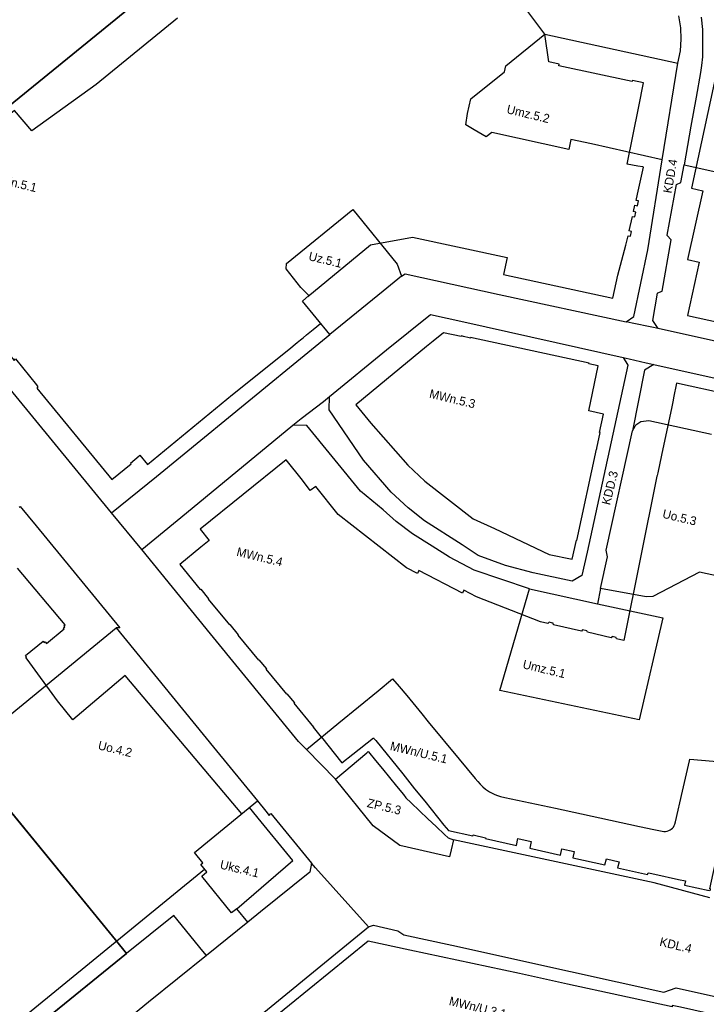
# Model space of a CAD drawing. Extents: x 7429686 to 7432896, y 5547954 to 5550600.
# Drawn here: x 7430853.5 to 7431167.9, y 5549633.8 to 5550085.1 of the extents above; entities that cross this region are included whole.
import ezdxf

# ---------------------------------------------------------------- set-up
doc = ezdxf.new("R2010")
doc.units = 0
for name, color, linetype in [('granica planu', 7, 'Continuous'), ('linie rozgraniczające', 7, 'Continuous'), ('obowiązująca linia zabudowy', 7, 'Continuous'), ('oznaczenia przeznaczeń', 7, 'Continuous')]:
    doc.layers.add(name, color=color, linetype=linetype)

msp = doc.modelspace()

# ---------------------------------------------------------------- linework, layer by layer
at = {"layer": 'granica planu'}
msp.add_lwpolyline([(7430718.8, 5549938.87), (7430746.03, 5549960.72), (7430798.13, 5550004.59), (7430923.69, 5550106.91), (7431051.87, 5550217.85), (7431132.58, 5550281.48)], dxfattribs=at)
at = {"layer": 'linie rozgraniczające'}
for p, q in [((7430897.36, 5549663.3), (7430837.38, 5549736.73)), ((7430902.46, 5549657.05), (7430897.36, 5549663.3)), ((7430805.78, 5549578.76), (7430902.46, 5549657.05))]:
    msp.add_line(p, q, dxfattribs=at)
for points in [[(7430973.53, 5550150.05), (7430923.69, 5550106.91), (7430798.13, 5550004.59), (7430788.04, 5549996.1)], [(7431156.31, 5550081.44), (7431155.42, 5550086.86)], [(7431165.53, 5550086.29), (7431166.21, 5550080.63)], [(7431156.47, 5550076.26), (7431156.31, 5550081.44)], [(7431076.18, 5550063.91), (7431093.98, 5550078.43)], [(7431093.98, 5550078.43), (7431154.96, 5550065.25)], [(7431166.21, 5550080.63), (7431166.23, 5550068.12)], [(7431156.14, 5550070.9), (7431156.47, 5550076.26)], [(7431154.96, 5550065.25), (7431156.14, 5550070.9)], [(7431166.23, 5550068.12), (7431165.7, 5550064.07)], [(7431075.58, 5550061.25), (7431076.18, 5550063.91)], [(7431147.66, 5550020.92), (7431154.96, 5550065.25)], [(7431165.7, 5550064.07), (7431165.28, 5550060.89)], [(7431060.15, 5550048.89), (7431075.58, 5550061.25)], [(7431165.28, 5550060.89), (7431163.27, 5550049.65)], [(7431163.27, 5550049.65), (7431160.91, 5550036.37)], [(7431058.61, 5550042.1), (7431060.15, 5550048.89)], [(7431057.86, 5550036.93), (7431058.61, 5550042.1)], [(7431061.63, 5550034.71), (7431057.86, 5550036.93)], [(7431160.91, 5550036.37), (7431157.75, 5550018.66)], [(7431067.14, 5550031.47), (7431061.63, 5550034.71)], [(7431069.76, 5550033.37), (7431067.14, 5550031.47)], [(7431104.9, 5550025.63), (7431069.76, 5550033.37)], [(7431105.91, 5550030.24), (7431104.9, 5550025.63)], [(7431115.3, 5550028.18), (7431105.91, 5550030.24)], [(7431147.66, 5550020.92), (7431115.3, 5550028.18)], [(7431141.08, 5549979.64), (7431147.66, 5550020.92)], [(7431156.3, 5550010.57), (7431157.75, 5550018.66)], [(7431157.75, 5550018.66), (7431245.1, 5549999.15)], [(7431150.04, 5549986.32), (7431154.22, 5550009.6)], [(7431154.22, 5550009.6), (7431156.3, 5550010.57)], [(7430975.74, 5549973.33), (7431006.02, 5549998.06)], [(7431006.02, 5549998.06), (7431026.42, 5549973.04)], [(7431150, 5549986.14), (7431150.04, 5549986.32)], [(7431147.71, 5549960.7), (7431151.82, 5549984.17)], [(7431151.82, 5549984.17), (7431150, 5549986.14)], [(7431134.71, 5549949.01), (7431141.08, 5549979.64)], [(7430975.49, 5549970.91), (7430975.74, 5549973.33)], [(7431026.42, 5549973.04), (7431028.33, 5549967.62)], [(7430982.3, 5549962.39), (7430975.49, 5549970.91)], [(7431028.33, 5549967.62), (7431029.95, 5549968.57)], [(7431029.95, 5549968.57), (7431073.1, 5549959.24)], [(7431028.33, 5549967.62), (7431019.89, 5549960.72)], [(7430985.82, 5549958.67), (7430982.3, 5549962.39)], [(7431019.89, 5549960.72), (7430995.5, 5549940.79)], [(7431073.1, 5549959.24), (7431131.18, 5549946.71)], [(7431143.5, 5549947.17), (7431145.65, 5549959.84)], [(7431145.65, 5549959.84), (7431145.7, 5549959.86)], [(7431145.7, 5549959.86), (7431147.71, 5549960.7)], [(7430982.97, 5549956.13), (7430985.82, 5549958.67)], [(7430995.5, 5549940.79), (7430982.97, 5549956.13)], [(7431021.5, 5549933.84), (7431041.68, 5549950)], [(7431041.68, 5549950), (7431056.88, 5549946.7)], [(7431056.88, 5549946.7), (7431129.85, 5549930.31)], [(7431131.18, 5549946.71), (7431134.71, 5549949.01)], [(7431134.04, 5549946.09), (7431131.18, 5549946.71)], [(7431142.99, 5549944.22), (7431134.04, 5549946.09)], [(7431145.92, 5549943.57), (7431143.5, 5549947.17)], [(7431145.92, 5549943.57), (7431142.99, 5549944.22)], [(7431228.11, 5549925.18), (7431145.92, 5549943.57)], [(7430975.4, 5549924.35), (7430995.5, 5549940.79)], [(7430995.4, 5549912.44), (7431021.5, 5549933.84)], [(7431129.85, 5549930.31), (7431132.67, 5549929.68)], [(7431129.85, 5549930.31), (7431132.04, 5549926.82)], [(7431132.67, 5549929.68), (7431140.35, 5549927.86)], [(7431140.35, 5549927.86), (7431143.92, 5549927.01)], [(7430895.54, 5549859.01), (7430842.76, 5549923.45)], [(7430969.47, 5549919.5), (7430975.4, 5549924.35)], [(7431132.04, 5549926.82), (7431113.29, 5549840.98)], [(7431139.69, 5549924.53), (7431134.17, 5549896.63)], [(7431143.92, 5549927.01), (7431139.69, 5549924.53)], [(7431143.92, 5549927.01), (7431223.5, 5549909.33)], [(7430916.17, 5549875.78), (7430969.47, 5549919.5)], [(7430982.36, 5549902.38), (7430992.57, 5549910.12)], [(7430992.57, 5549910.12), (7430995.4, 5549912.44)], [(7430995.2, 5549906.25), (7430995.4, 5549912.44)], [(7431010.91, 5549883.15), (7430995.2, 5549906.25)], [(7430978.51, 5549899.2), (7430982.36, 5549902.38)], [(7431135.59, 5549899.35), (7431138, 5549900.89)], [(7431138, 5549900.89), (7431141.55, 5549901.35)], [(7431141.55, 5549901.35), (7431170.32, 5549895.1)], [(7430929.85, 5549859.07), (7430978.51, 5549899.2)], [(7430985.05, 5549899.09), (7430978.51, 5549899.2)], [(7431009.63, 5549869.06), (7430985.05, 5549899.09)], [(7431122.13, 5549841.96), (7431134.17, 5549896.63)], [(7431134.17, 5549896.63), (7431135.32, 5549898.83)], [(7431135.32, 5549898.83), (7431135.59, 5549899.35)], [(7431023.63, 5549868.54), (7431010.91, 5549883.15)], [(7430895.54, 5549859.01), (7430916.17, 5549875.78)], [(7431019.93, 5549860.45), (7431009.63, 5549869.06)], [(7431031.39, 5549861.42), (7431023.63, 5549868.54)], [(7430853.19, 5549861.61), (7430853.71, 5549862.02)], [(7430853.71, 5549862.02), (7430860.95, 5549853.17)], [(7431025.91, 5549855.18), (7431019.93, 5549860.45)], [(7431038.94, 5549855.4), (7431031.39, 5549861.42)], [(7430909.35, 5549842.32), (7430895.54, 5549859.01)], [(7430909.35, 5549842.32), (7430929.85, 5549859.07)], [(7431056.08, 5549844.45), (7431038.94, 5549855.4)], [(7430860.95, 5549853.17), (7430894.39, 5549812.29)], [(7431033.33, 5549849.46), (7431025.91, 5549855.18)], [(7431042.32, 5549843.83), (7431033.33, 5549849.46)], [(7430940.83, 5549803.67), (7430909.35, 5549842.32)], [(7431050.35, 5549838.8), (7431042.32, 5549843.83)], [(7431063.43, 5549839.56), (7431056.08, 5549844.45)], [(7431122.61, 5549838.95), (7431122.13, 5549841.96)], [(7431061.54, 5549832.74), (7431050.35, 5549838.8)], [(7431075.89, 5549834.93), (7431063.43, 5549839.56)], [(7431113.29, 5549840.98), (7431110.87, 5549830.29)], [(7431119.53, 5549824.34), (7431122.61, 5549838.95)], [(7431086.88, 5549824.29), (7431061.54, 5549832.74)], [(7431088.7, 5549831.64), (7431075.89, 5549834.93)], [(7431106.55, 5549827.77), (7431088.7, 5549831.64)], [(7431110.87, 5549830.29), (7431106.55, 5549827.77)], [(7431164.77, 5549831.94), (7431143.47, 5549820.73)], [(7431190.87, 5549826.26), (7431164.77, 5549831.94)], [(7431073.36, 5549777.62), (7431086.88, 5549824.29)], [(7431086.88, 5549824.29), (7431118.14, 5549817.3)], [(7431119.53, 5549824.34), (7431118.14, 5549817.3)], [(7431140.43, 5549820.55), (7431119.53, 5549824.34)], [(7431143.47, 5549820.73), (7431140.43, 5549820.55)], [(7431118.14, 5549817.3), (7431148.09, 5549810.95)], [(7430894.39, 5549812.29), (7430899.27, 5549806.33)], [(7431148.09, 5549810.95), (7431137.25, 5549764.16)], [(7430843.03, 5549761.55), (7430897.72, 5549806.4)], [(7430899.27, 5549806.33), (7430897.72, 5549806.4)], [(7430897.72, 5549806.4), (7430942.25, 5549751.7)], [(7430981.18, 5549754.2), (7430940.83, 5549803.67)], [(7431017.58, 5549777.52), (7431024.2, 5549782.96)], [(7431024.2, 5549782.96), (7431027.25, 5549779.49)], [(7431027.25, 5549779.49), (7431030.77, 5549775.35)], [(7430999.7, 5549762.83), (7431017.58, 5549777.52)], [(7431030.77, 5549775.35), (7431037.59, 5549767.01)], [(7431137.25, 5549764.16), (7431073.36, 5549777.62)], [(7431037.59, 5549767.01), (7431040.6, 5549763.25)], [(7430843.03, 5549761.55), (7430837.33, 5549756.8), (7430844.84, 5549747.74), (7430847.43, 5549744.63), (7430837.38, 5549736.73), (7430897.36, 5549663.3), (7430902.46, 5549657.05)], [(7430984.78, 5549750.53), (7430999.7, 5549762.83)], [(7431040.6, 5549763.25), (7431054.81, 5549746.21)], [(7430942.25, 5549751.7), (7430962.34, 5549727)], [(7430984.78, 5549750.53), (7430981.18, 5549754.2)], [(7430998.08, 5549737.02), (7430984.78, 5549750.53)], [(7430998.08, 5549737.02), (7431012.44, 5549749.08)], [(7431012.44, 5549749.08), (7431013.1, 5549749.64)], [(7431013.1, 5549749.64), (7431013.21, 5549749.52)], [(7431013.21, 5549749.52), (7431016.43, 5549745.59)], [(7431016.43, 5549745.59), (7431019.65, 5549741.66)], [(7431054.81, 5549746.21), (7431062.11, 5549737.37)], [(7431157.03, 5549731.55), (7431160.23, 5549745.43)], [(7431160.23, 5549745.43), (7431160.38, 5549746.12)], [(7431160.38, 5549746.12), (7431212.2, 5549741.68)], [(7431019.65, 5549741.66), (7431022.86, 5549737.73)], [(7431015.34, 5549715.58), (7430998.08, 5549737.02)], [(7431022.86, 5549737.73), (7431026.08, 5549733.8)], [(7431026.08, 5549733.8), (7431029.26, 5549729.92)], [(7431062.11, 5549737.37), (7431063.28, 5549735.87)], [(7431063.28, 5549735.87), (7431064.3, 5549734.76)], [(7431064.3, 5549734.76), (7431065.59, 5549733.44)], [(7431065.59, 5549733.44), (7431066.81, 5549732.47)], [(7431029.26, 5549729.92), (7431030.3, 5549728.47)], [(7431066.81, 5549732.47), (7431068.69, 5549731.18)], [(7431068.69, 5549731.18), (7431069.83, 5549730.55)], [(7431069.83, 5549730.55), (7431071.06, 5549729.96)], [(7431071.06, 5549729.96), (7431072.27, 5549729.5)], [(7431072.27, 5549729.5), (7431073.68, 5549729.1)], [(7431073.68, 5549729.1), (7431075.73, 5549728.67)], [(7431153.84, 5549717.44), (7431157.03, 5549731.55)], [(7430933.54, 5549703.36), (7430962.34, 5549727)], [(7430962.34, 5549727), (7430966.16, 5549722.31)], [(7431030.3, 5549728.47), (7431032.8, 5549726.1)], [(7431032.8, 5549726.1), (7431036.59, 5549722.49)], [(7431075.73, 5549728.67), (7431098.89, 5549723.67)], [(7430966.16, 5549722.31), (7430967.72, 5549720.4)], [(7430967.72, 5549720.4), (7430968.56, 5549721.26)], [(7430968.56, 5549721.26), (7430987.05, 5549698.56)], [(7431036.59, 5549722.49), (7431040.39, 5549718.88)], [(7431098.89, 5549723.67), (7431110.74, 5549721.08)], [(7431110.74, 5549721.08), (7431137.3, 5549715.28)], [(7431027.5, 5549706.57), (7431015.34, 5549715.58)], [(7431040.39, 5549718.88), (7431044.18, 5549715.28)], [(7431152.83, 5549715.04), (7431153.25, 5549715.7)], [(7431153.25, 5549715.7), (7431153.59, 5549716.4)], [(7431153.59, 5549716.4), (7431153.84, 5549717.44)], [(7431044.18, 5549715.28), (7431047.98, 5549711.67)], [(7431047.98, 5549711.67), (7431049.65, 5549710.08)], [(7431137.3, 5549715.28), (7431143.9, 5549713.86)], [(7431143.9, 5549713.86), (7431148.5, 5549713.02)], [(7431148.5, 5549713.02), (7431149.2, 5549713.05)], [(7431149.2, 5549713.05), (7431150.06, 5549713.2)], [(7431150.06, 5549713.2), (7431150.82, 5549713.46)], [(7431150.82, 5549713.46), (7431151.36, 5549713.74)], [(7431151.36, 5549713.74), (7431151.83, 5549714.07)], [(7431151.83, 5549714.07), (7431152.47, 5549714.61)], [(7431152.47, 5549714.61), (7431152.83, 5549715.04)], [(7431046.98, 5549702.13), (7431027.5, 5549706.57)], [(7431049.65, 5549710.08), (7431052.1, 5549709.26)], [(7431052.1, 5549709.26), (7431051.09, 5549704.66)], [(7431144.11, 5549689.49), (7431052.1, 5549709.26)], [(7430937.31, 5549698.72), (7430933.54, 5549703.36)], [(7431050.37, 5549701.36), (7431046.98, 5549702.13)], [(7431051.09, 5549704.66), (7431050.37, 5549701.36)], [(7430936.36, 5549697.95), (7430937.31, 5549698.72)], [(7430937.83, 5549696.14), (7430936.36, 5549697.95)], [(7430987.05, 5549698.56), (7430986.42, 5549694.32)], [(7430988.89, 5549696.3), (7430987.05, 5549698.56)], [(7430936.85, 5549692.54), (7430939.21, 5549694.45)], [(7430939.21, 5549694.45), (7430937.83, 5549696.14)], [(7430986.42, 5549694.32), (7430963.78, 5549676.12)], [(7431013.19, 5549669.37), (7430988.89, 5549696.3)], [(7430950.54, 5549675.71), (7430936.85, 5549692.54)], [(7431169.5, 5549682.54), (7431144.11, 5549689.49)], [(7430952.89, 5549677.63), (7430950.54, 5549675.71)], [(7430957.93, 5549671.42), (7430952.89, 5549677.63)], [(7430963.78, 5549676.12), (7430957.93, 5549671.42)], [(7430924.01, 5549674.5), (7430902.46, 5549657.05)], [(7430937.37, 5549658.14), (7430924.01, 5549674.5)], [(7430957.93, 5549671.42), (7430938.97, 5549656.18)], [(7430948.56, 5549616.32), (7431013.19, 5549669.37)], [(7431013.19, 5549669.37), (7431015.5, 5549670.12)], [(7431015.5, 5549670.12), (7431026.68, 5549667.55)], [(7431026.68, 5549667.55), (7431029.35, 5549665.59)], [(7431029.35, 5549665.59), (7431051.4, 5549660.88)], [(7430902.46, 5549657.05), (7430805.78, 5549578.76)], [(7430938.97, 5549656.18), (7430937.37, 5549658.14)], [(7431051.4, 5549660.88), (7431105.76, 5549648.85)], [(7430938.97, 5549656.18), (7430912.39, 5549634.82)], [(7431105.76, 5549648.85), (7431148.44, 5549639.39)], [(7431148.44, 5549639.39), (7431154.15, 5549641.32)], [(7431154.15, 5549641.32), (7431217.12, 5549627.23)], [(7430912.39, 5549634.82), (7430824.34, 5549562.34)]]:
    msp.add_lwpolyline(points, dxfattribs=at)
at = {"layer": 'obowiązująca linia zabudowy'}
for p, q in [((7430925.76, 5550085.9), (7430888.49, 5550055.45)), ((7430888.49, 5550055.45), (7430859.07, 5550034.17)), ((7430888.49, 5550055.45), (7430888.49, 5550055.45)), ((7430888.49, 5550055.45), (7430888.49, 5550055.45)), ((7431138.85, 5550017.61), (7431136.58, 5550018.02)), ((7430985.41, 5549958.3), (7430985.41, 5549958.3)), ((7431042.83, 5549937.8), (7431039.84, 5549935.34)), ((7431042.83, 5549937.8), (7431042.83, 5549937.8)), ((7431055.66, 5549939.9), (7431055.66, 5549939.9)), ((7431039.84, 5549935.34), (7431039.84, 5549935.34)), ((7430861.12, 5549917.74), (7430861.12, 5549917.74)), ((7430861.12, 5549917.74), (7430861.8, 5549916.9)), ((7430908.24, 5549885.19), (7430908.24, 5549885.19)), ((7430982.94, 5549873.99), (7430982.94, 5549873.99)), ((7431095.98, 5549808.91), (7431095.98, 5549808.9)), ((7430901.77, 5549784.45), (7430877.85, 5549764.2)), ((7430955.25, 5549721.18), (7430901.77, 5549784.45)), ((7430991.72, 5549756.25), (7430991.72, 5549756.25)), ((7431031.06, 5549736.68), (7431031.06, 5549736.68)), ((7431031.06, 5549736.68), (7431034.33, 5549732.63)), ((7431034.33, 5549732.63), (7431034.33, 5549732.63)), ((7431034.33, 5549732.63), (7431038.97, 5549726.88)), ((7431038.97, 5549726.88), (7431038.97, 5549726.88)), ((7431061.08, 5549711.43), (7431061.08, 5549711.43)), ((7431141.04, 5549693.33), (7431141.29, 5549694.04)), ((7431144.34, 5549693.38), (7431144.34, 5549693.38))]:
    msp.add_line(p, q, dxfattribs=at)
for points in [[(7431150.34, 5550144.25), (7431155, 5550138.59), (7431165.07, 5550121.75), (7431172.7, 5550105.48), (7431174.01, 5550089.79), (7431174.15, 5550071.53), (7431171.53, 5550056.01), (7431161.22, 5550007.85)], [(7431093.98, 5550078.43), (7431085.78, 5550089.45), (7431084.03, 5550091.53)], [(7431136.58, 5550018.02), (7431131.65, 5550018.92), (7431137.03, 5550045.32), (7431139.24, 5550056.14), (7431134.09, 5550057.24), (7431134, 5550056.8), (7431100.41, 5550063.97), (7431100.58, 5550064.69), (7431095.83, 5550065.82), (7431093.98, 5550078.43)], [(7430859.07, 5550034.17), (7430851.15, 5550043.55), (7430807.39, 5550008.18), (7430809.47, 5550005.9)], [(7431127.48, 5549968.1), (7431131.09, 5549981.76), (7431132.11, 5549986.07), (7431133.19, 5549985.89), (7431133.67, 5549988.07), (7431132.63, 5549988.35), (7431134.1, 5549994.91), (7431135.2, 5549994.69), (7431135.68, 5549996.89), (7431134.59, 5549997.15), (7431135.27, 5550000.04), (7431136.36, 5549999.86), (7431136.83, 5550002.04), (7431135.75, 5550002.31), (7431136.49, 5550005.15), (7431139.16, 5550017.55), (7431138.85, 5550017.61)], [(7430809.47, 5550005.9), (7430796.29, 5549995.12), (7430796.34, 5549995.06), (7430850.88, 5549928.94), (7430851.52, 5549929.64), (7430861.12, 5549917.74)], [(7431161.22, 5550007.85), (7431166.34, 5550006.72), (7431159.36, 5549975.18)], [(7430985.41, 5549958.3), (7431014.08, 5549981.96)], [(7431014.08, 5549981.96), (7431033.3, 5549985.52), (7431076.71, 5549976.11)], [(7431076.71, 5549976.11), (7431074.98, 5549968.27)], [(7431164.73, 5549974.03), (7431159.32, 5549949.51), (7431209.59, 5549938.54)], [(7431159.36, 5549975.18), (7431164.73, 5549974.03)], [(7431074.98, 5549968.27), (7431125.07, 5549957.48), (7431127.48, 5549968.1)], [(7430982.08, 5549938.35), (7430983.23, 5549939.29), (7430984.85, 5549940.62), (7430985.65, 5549941.28), (7430987.19, 5549942.53), (7430987.95, 5549943.16), (7430989.58, 5549944.5), (7430991.28, 5549945.89)], [(7431055.66, 5549939.9), (7431047.52, 5549941.66), (7431042.83, 5549937.8)], [(7430950.95, 5549913.35), (7430976.68, 5549933.92), (7430980.58, 5549937.12)], [(7430980.58, 5549937.12), (7430980.58, 5549937.12), (7430982.07, 5549938.35), (7430982.08, 5549938.35)], [(7431056.67, 5549939.97), (7431055.75, 5549940.19), (7431055.66, 5549939.9)], [(7431056.67, 5549939.96), (7431056.67, 5549939.97)], [(7431059.28, 5549939.33), (7431059.28, 5549939.32), (7431056.67, 5549939.96)], [(7431114.08, 5549905.84), (7431118.36, 5549926.46), (7431114.15, 5549927.39), (7431114.24, 5549927.72), (7431059.93, 5549939.51), (7431059.88, 5549939.19), (7431059.28, 5549939.33)], [(7431039.84, 5549935.34), (7431021.53, 5549920.26), (7431007.39, 5549908.62)], [(7431201.53, 5549908.12), (7431154.23, 5549918.55), (7431152.93, 5549911.84), (7431152.72, 5549910.76), (7431152.14, 5549907.74)], [(7430861.12, 5549917.74), (7430861.12, 5549917.74)], [(7430861.8, 5549916.9), (7430861.29, 5549916.29), (7430895.6, 5549874.31), (7430904.53, 5549881.53), (7430904.29, 5549881.83)], [(7430904.29, 5549881.83), (7430908.24, 5549885.19), (7430908.56, 5549885.46), (7430912.01, 5549881.25), (7430950.95, 5549913.35)], [(7431007.39, 5549908.62), (7431014.33, 5549900.24), (7431031.21, 5549880.99), (7431039.08, 5549873.64), (7431061.1, 5549856.33), (7431071, 5549851.87), (7431096.03, 5549840.05), (7431106.43, 5549837.77), (7431108.43, 5549846.54), (7431108.68, 5549846.43), (7431117.71, 5549888.31)], [(7431117.8, 5549888.72), (7431119.34, 5549895.84), (7431119.02, 5549895.88), (7431120.9, 5549904.37), (7431114.08, 5549905.84)], [(7431152.14, 5549907.74), (7431147.43, 5549885.51), (7431145.67, 5549877.49), (7431145.38, 5549876.13), (7431145.32, 5549875.89)], [(7430982.94, 5549873.99), (7430975.5, 5549883.31), (7430936.12, 5549851.54), (7430940.19, 5549846.45), (7430936.49, 5549843.27)], [(7430999.38, 5549858.33), (7430989.1, 5549871.16), (7430986.53, 5549869.27), (7430982.94, 5549873.99)], [(7431145.32, 5549875.89), (7431130.2, 5549800.54), (7431126.86, 5549801.34), (7431126.59, 5549801.97), (7431124.83, 5549802.32), (7431124.29, 5549801.82), (7431113.47, 5549804.37), (7431113.26, 5549804.94), (7431111.23, 5549805.45), (7431110.74, 5549804.91), (7431097.93, 5549807.79), (7431097.85, 5549808.54), (7431096.99, 5549808.71), (7431095.98, 5549808.91)], [(7431062.62, 5549820.53), (7431056.9, 5549823.62), (7431056.23, 5549822.19), (7431036.3, 5549832.61), (7431035.61, 5549831.25), (7431030.61, 5549833.85), (7430999.38, 5549858.33)], [(7430936.49, 5549843.27), (7430926.81, 5549835.34), (7430936.2, 5549823.91), (7430936.38, 5549824.07), (7430939.96, 5549819.71), (7430939.77, 5549819.56), (7430949.52, 5549807.69), (7430949.74, 5549807.87), (7430953.56, 5549803.22), (7430953.34, 5549803.04), (7430962.81, 5549791.51), (7430963.05, 5549791.7), (7430966.45, 5549787.57), (7430966.21, 5549787.37), (7430975.61, 5549775.91), (7430975.85, 5549776.11), (7430979.26, 5549771.96), (7430979.02, 5549771.76), (7430987.96, 5549760.88)], [(7430877.85, 5549764.2), (7430870.86, 5549772.91), (7430856.89, 5549791.93), (7430856.23, 5549792.75), (7430856.59, 5549793.04), (7430856.08, 5549793.67), (7430864.25, 5549800.25), (7430864.71, 5549799.68), (7430865.09, 5549799.99), (7430865.8, 5549799.11), (7430873.87, 5549805.89), (7430873.51, 5549806.33), (7430874.11, 5549806.84), (7430873.74, 5549807.27), (7430874.3, 5549807.74), (7430852.44, 5549833.69)], [(7431095.98, 5549808.91), (7431095.89, 5549808.92), (7431095.4, 5549808.39), (7431091.94, 5549809.15), (7431062.62, 5549820.53)], [(7431095.98, 5549808.9), (7431095.98, 5549808.91)], [(7430991.72, 5549756.25), (7430987.96, 5549760.88), (7430987.96, 5549760.88)], [(7430991.72, 5549756.25), (7431001.08, 5549744.51), (7431006.01, 5549748.4), (7431015.53, 5549755.91)], [(7431015.53, 5549755.91), (7431015.7, 5549755.7), (7431016.55, 5549754.66), (7431028.87, 5549739.39), (7431031.06, 5549736.68)], [(7431031.06, 5549736.68), (7431031.06, 5549736.68)], [(7431034.33, 5549732.63), (7431034.33, 5549732.63)], [(7431038.97, 5549726.88), (7431038.97, 5549726.88)], [(7431038.97, 5549726.88), (7431047.79, 5549715.95), (7431049.82, 5549713.44), (7431061, 5549711.09), (7431061.08, 5549711.43)], [(7430952.89, 5549677.63), (7430978.61, 5549699.76), (7430975.88, 5549703.13), (7430964.14, 5549717.43), (7430958.73, 5549724.03)], [(7431144.34, 5549693.38), (7431155.14, 5549691.05), (7431158.35, 5549690.36), (7431157.96, 5549688.36), (7431169.25, 5549685.92), (7431169.32, 5549686.22), (7431169.79, 5549686.12), (7431169.91, 5549686.68), (7431169.53, 5549686.77), (7431176.28, 5549717.57), (7431176.56, 5549717.5), (7431176.72, 5549718.22), (7431176.06, 5549718.37), (7431176.96, 5549722.4)], [(7431061.08, 5549711.43), (7431066.81, 5549710.05), (7431066.75, 5549709.81), (7431080.99, 5549706.66), (7431081.67, 5549709.73), (7431087.75, 5549708.38), (7431087.07, 5549705.31), (7431101.13, 5549702.19), (7431101.77, 5549705.09), (7431107.46, 5549703.83), (7431106.82, 5549700.92), (7431121.53, 5549697.66), (7431122.22, 5549700.46), (7431128.01, 5549699.16), (7431127.29, 5549696.38), (7431141.04, 5549693.33)], [(7430807.75, 5549615.61), (7430820.21, 5549600.01), (7430823.08, 5549602.43), (7430823.42, 5549602.03), (7430938.16, 5549695.73)], [(7431141.29, 5549694.04), (7431142.15, 5549693.86), (7431144.34, 5549693.38)], [(7431082.3, 5549647.94), (7431032.15, 5549658.64), (7431013.1, 5549662.7), (7430950.02, 5549611.38), (7430935.36, 5549599.38)], [(7431228.2, 5549614.94), (7431228.3, 5549615.39), (7431214.88, 5549618.58), (7431215.1, 5549619.26), (7431213.86, 5549619.54), (7431156.17, 5549632.45), (7431152.34, 5549633.31), (7431152.22, 5549632.57), (7431104.29, 5549643.07), (7431082.3, 5549647.94)]]:
    msp.add_lwpolyline(points, dxfattribs=at)
msp.add_arc((7431118.04, 5549888.45), 0.364, 132.3562, 202.8823, dxfattribs=at)

# ---------------------------------------------------------------- texts
at = {"layer": 'oznaczenia przeznaczeń'}
for s, rotation, p in [('Umz.5.2', 346.4891, (7431076.22, 5550042.34)), ('KDD.4', 80.0304, (7431152, 5550005.33)), ('MWn.5.1', 346.4891, (7430839.96, 5550011.04)), ('Uz.5.1', 346.4891, (7430985.5, 5549974.97)), ('MWn.5.3', 346.4891, (7431040.79, 5549911.95)), ('KDD.3', 76.3287, (7431123.83, 5549862.39)), ('Uo.5.3', 346.4891, (7431147.56, 5549856.88)), ('MWn.5.4', 346.4891, (7430952.53, 5549839.47)), ('Umz.5.1', 346.5122, (7431083.56, 5549787.89)), ('Uo.4.2', 346.4891, (7430889.06, 5549750.74)), ('MWn/U.5.1', 346.4891, (7431022.82, 5549750.42)), ('ZP.5.3', 346.4891, (7431012.27, 5549724.3)), ('Uks.4.1', 346.4891, (7430944.93, 5549696.11)), ('KDL.4', 346.4891, (7431146.26, 5549660.72)), ('MWn/U.3.1', 346.4891, (7431049.82, 5549633.54))]:
    msp.add_text(s, height=4, rotation=rotation, dxfattribs=at).set_placement(p)

doc.saveas('drawing.dxf')
